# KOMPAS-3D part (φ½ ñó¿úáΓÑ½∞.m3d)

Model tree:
1. Эскиз:1
2. Операция выдавливания:1
     Расстояние 1 = 18
3. Эскиз:2
4. Операция выдавливания:2
     Расстояние 1 = 1
5. Эскиз:3
6. Операция выдавливания:3
     Расстояние 1 = 10
7. Эскиз:4
8. Операция выдавливания:4
     Расстояние 1 = 2
9. Эскиз:5
10. Операция выдавливания:5
     Расстояние 1 = 2; Расстояние 2 = 5
11. Эскиз:7
12. Операция выдавливания:6
     Расстояние 1 = 2; Расстояние 2 = 5
13. Массив по концентрической сетке:2  (with: Операция выдавливания:6, Операция выдавливания:5)  (labels: Экземпляр ( 1, 1 ); Экземпляр ( 1, 2 ); Экземпляр ( 1, 3 ); Экземпляр ( 1, 4 ))
     N 2 = 8; Шаг 2 = 360; Номер 2 = 1
14. Эскиз:8
15. Операция выдавливания:7
     Расстояние 1 = 1; Расстояние 2 = 5
